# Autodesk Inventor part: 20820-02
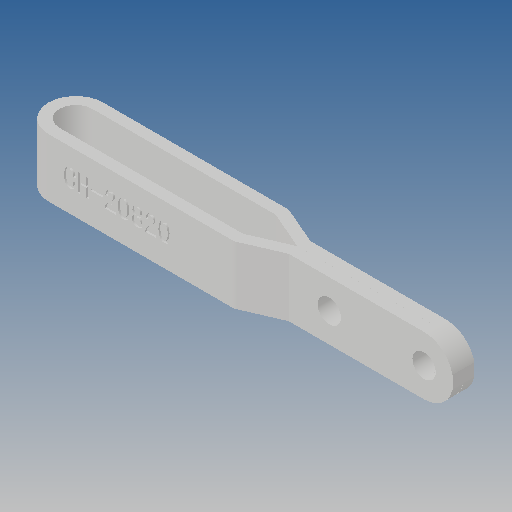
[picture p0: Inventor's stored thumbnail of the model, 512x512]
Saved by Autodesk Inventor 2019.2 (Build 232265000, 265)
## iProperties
Created: 2011-12
Part Number: 20820-02
Material: Ogólny
Document SubType Name: Modeling
Designer: CADENGINEERING4
Density: 1 g/cm^3
Appearance: Domyślna
Author: CADENGINEERING4
Revision Number: ÈÎºÎ
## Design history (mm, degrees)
feature "ÇÐ³ý-À­Éì3"
feature "ÇÐ³ý-À­Éì4"
node "Bryła1"
node "Bryła2"
